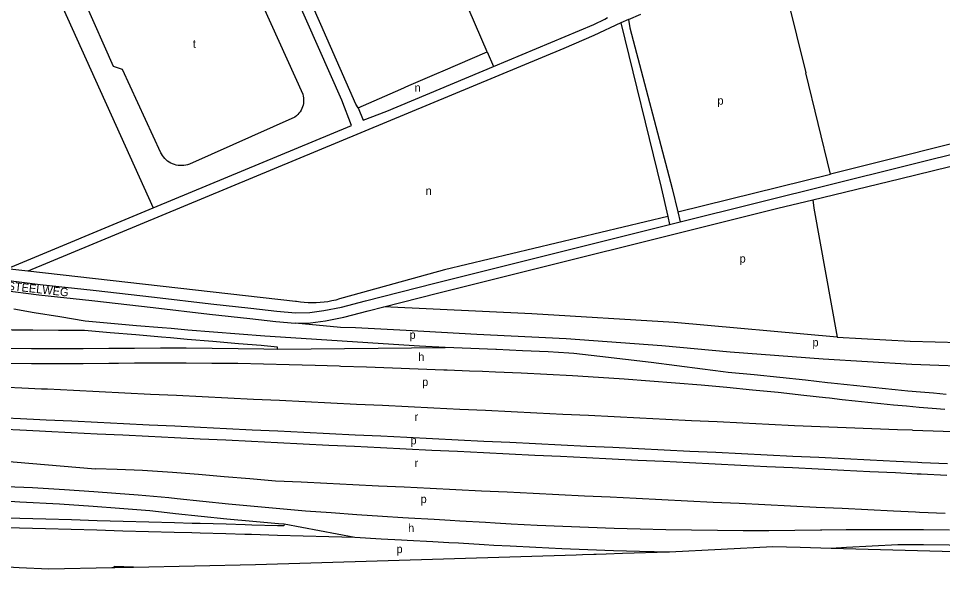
# Model space of a CAD drawing. Extents: x 161093 to 163177, y 379000 to 380904.
# Drawn here: x 161621 to 162069, y 379501.4 to 379771.7 of the extents above; entities that cross this region are included whole.
import ezdxf

# ---------------------------------------------------------------- set-up
doc = ezdxf.new("R2010")
doc.units = 0
for name, color, linetype in [('BLT_Basislijn', 7, 'Continuous'), ('BLT_Centroide', 7, 'Continuous'), ('BLT_Gemeentegrens', 7, 'Continuous'), ('BLT_Hoogspanningsmast_en_leidingen', 7, 'Continuous'), ('BLT_Straatnaam_verkleind', 7, 'Continuous'), ('BLT_Vlakafsluiter', 7, 'Continuous')]:
    doc.layers.add(name, color=color, linetype=linetype)

msp = doc.modelspace()

# ---------------------------------------------------------------- linework, layer by layer
at = {"layer": 'BLT_Basislijn'}
for p, q in [((161631.7, 379800.84), (161686.42, 379679.79)), ((161992.33, 379787.49), (162002.81, 379745.28)), ((161916.83, 379771.19), (161922.76, 379773.7)), ((161916.83, 379771.19), (161912.99, 379769.51)), ((161848.26, 379755.5), (161851.28, 379748.35)), ((162014.73, 379696.21), (162002.81, 379745.28)), ((161755.03, 379723.83), (161703.94, 379701.04)), ((161940.66, 379677.86), (162014.73, 379696.21)), ((161941.83, 379673), (162015.88, 379691.47)), ((161615.34, 379650.24), (161686.42, 379679.79)), ((161935.83, 379675.66), (161827.59, 379649.74)), ((161935.83, 379675.66), (161936.74, 379671.73)), ((161940.66, 379677.86), (161941.83, 379673)), ((161822.91, 379643.33), (161936.74, 379671.73)), ((161936.74, 379671.73), (161941.83, 379673)), ((161625.61, 379649.08), (161615.34, 379650.24)), ((161755.33, 379634.38), (161625.61, 379649.08)), ((161827.59, 379649.74), (161778.52, 379636.18)), ((162054.48, 379571.89), (162115.85, 379569.9)), ((161607.31, 379557.54), (161658.4, 379553.21))]:
    msp.add_line(p, q, dxfattribs=at)
for points in [[(161716.02, 379826.76), (161726.38, 379805.69), (161724.49, 379804.29), (161729.14, 379793.95), (161731.73, 379795.11), (161758.83, 379734.88)], [(161848.26, 379755.5), (161830.87, 379796.01), (161818.6, 379824.68)], [(161686.42, 379679.79), (161782.48, 379719.76), (161777.79, 379732.06), (161743.21, 379810.26)], [(161785.66, 379728.39), (161784.58, 379730.09), (161767.66, 379768.76), (161749.52, 379809.87)], [(161690.13, 379706.56), (161671.49, 379746.97), (161667.17, 379748.31), (161653.31, 379779.49), (161654.88, 379780.21), (161652.16, 379786.35)], [(161912.99, 379769.51), (161900, 379763.42), (161885.43, 379757.17), (161625.61, 379649.08)], [(161851.28, 379748.35), (161900, 379768.76), (161905.26, 379771.38), (161906.6, 379772.15)], [(161912.99, 379769.51), (161932.64, 379689.6), (161935.83, 379675.66)], [(161916.83, 379771.19), (161917.41, 379767.19), (161937.92, 379689.22), (161940.66, 379677.86)], [(161785.66, 379728.39), (161806.4, 379737.35), (161810.28, 379739.08), (161823.92, 379744.93), (161827, 379746.26), (161848.26, 379755.5)], [(161785.66, 379728.39), (161788.11, 379722.31), (161799.58, 379726.7), (161851.28, 379748.35)], [(162185.61, 379741.33), (162185.91, 379739.2), (162185.61, 379738.96), (162014.73, 379696.21)], [(162015.88, 379691.47), (162187.88, 379734.37), (162189.84, 379735.93), (162191.1, 379738.2), (162190.48, 379742.58)], [(161758.83, 379734.88), (161759.06, 379734.02), (161759.2, 379733.15), (161759.27, 379732.26), (161759.26, 379731.37), (161759.17, 379730.49), (161759, 379729.61), (161758.75, 379728.76), (161758.42, 379727.93), (161758.03, 379727.14), (161757.56, 379726.38), (161757.03, 379725.67), (161756.43, 379725.01), (161755.78, 379724.41), (161755.03, 379723.83)], [(162006.2, 379683.74), (162048.1, 379693.81), (162112.09, 379709.59), (162189.91, 379729.16), (162191.71, 379729.23), (162193.12, 379728.84), (162194.49, 379728.03)], [(161703.94, 379701.04), (161703.06, 379700.73), (161702.15, 379700.51), (161701.24, 379700.36), (161700.31, 379700.29), (161699.38, 379700.3), (161698.45, 379700.39), (161697.53, 379700.56), (161696.64, 379700.81), (161695.76, 379701.13), (161694.92, 379701.53), (161694.11, 379702), (161693.35, 379702.53), (161692.64, 379703.13), (161691.98, 379703.79), (161691.38, 379704.5), (161690.84, 379705.26), (161690.37, 379706.07), (161690.13, 379706.56)], [(161824.15, 379638.49), (161989.17, 379679.65), (162006.2, 379683.74)], [(162006.2, 379683.74), (162006.66, 379679.64), (162018.02, 379617.13)], [(161543.41, 379661.1), (161543.58, 379656.98), (161544.04, 379655.38), (161544.67, 379654.3), (161545.55, 379653.27), (161546.57, 379652.45), (161548.53, 379651.99), (161558.56, 379650.79), (161577.45, 379648.89), (161598.58, 379646.57), (161613.83, 379644.81), (161631.56, 379642.59), (161657.22, 379639.82), (161686.97, 379636.4), (161714.22, 379633.26), (161733.73, 379631.1), (161746.36, 379629.63), (161755.31, 379628.82), (161762.24, 379629.08), (161769.08, 379629.98), (161777.69, 379631.61), (161789.34, 379634.73), (161822.91, 379643.33)], [(161540.83, 379645.85), (161541.44, 379646.81), (161542.32, 379647.33), (161543.43, 379647.57), (161558.02, 379645.82), (161576.93, 379643.92), (161598.02, 379641.6), (161613.23, 379639.84), (161630.98, 379637.62), (161656.67, 379634.85), (161686.4, 379631.43), (161713.66, 379628.29), (161733.17, 379626.14), (161745.84, 379624.66), (161755.18, 379623.81)], [(161798.19, 379631.84), (161824.15, 379638.49)], [(161778.52, 379636.18), (161776.69, 379635.6), (161774.84, 379635.08), (161772.97, 379634.65), (161771.08, 379634.29), (161769.18, 379634.01), (161767.27, 379633.81), (161765.36, 379633.69), (161763.44, 379633.66), (161761.52, 379633.7), (161759.6, 379633.82), (161757.69, 379634.02), (161755.8, 379634.3), (161755.33, 379634.38)], [(161827.87, 379612.14), (161815.39, 379612.75), (161802.91, 379613.53), (161790.44, 379614.36), (161777.97, 379615.1), (161765.49, 379615.89), (161753.02, 379616.73), (161740.56, 379617.61), (161728.1, 379618.53), (161715.64, 379619.5), (161703.18, 379620.51), (161695, 379621.2), (161690.73, 379621.57), (161678.27, 379622.63), (161665.82, 379623.7), (161653.36, 379624.76), (161641.03, 379626.86), (161628.66, 379628.95), (161618.77, 379630.63)], [(161755.18, 379623.81), (161762.66, 379624.09), (161769.87, 379625.04), (161778.8, 379626.74), (161790.61, 379629.9), (161798.19, 379631.84)], [(162018.02, 379617.13), (161938.9, 379624.15), (161869.92, 379628.37), (161798.19, 379631.84)], [(161746.67, 379611.27), (161746.7, 379612.27), (161740.2, 379612.82), (161738.77, 379612.95), (161727.74, 379613.89), (161715.29, 379614.95), (161702.83, 379616.02), (161694.81, 379616.7), (161690.38, 379617.08), (161677.92, 379618.15), (161665.47, 379619.21), (161653.01, 379620.28), (161640.48, 379620.36), (161627.94, 379620.45), (161617.91, 379620.52), (161615.42, 379620.73), (161602.96, 379621.8), (161598.16, 379622.21), (161590.51, 379622.86), (161580.54, 379623.71), (161578.05, 379623.93), (161565.6, 379624.99), (161553.14, 379626.06)], [(162154.44, 379587.46), (162154.31, 379590.38), (162153.73, 379592.07), (162152.3, 379593.86), (162150.56, 379595.82), (162148.24, 379598.09), (162146.65, 379599.3), (162145.28, 379599.99), (162141.64, 379600.52), (162121.07, 379601.52), (162089.29, 379602.54), (162054.12, 379603.88), (162011.17, 379606.32), (161966.06, 379609.87), (161932.99, 379612.83), (161886.58, 379616.22), (161843.25, 379618.32), (161808.99, 379620.26), (161784.42, 379621.55), (161777.14, 379621.71)], [(162018.02, 379617.13), (162053.26, 379615.11), (162101.88, 379613.84), (162118.38, 379613.34), (162131.74, 379613.09), (162132.12, 379609.94), (162171.47, 379608.91)], [(161542.18, 379613.94), (161544.61, 379613.83), (161552.7, 379613.46), (161565.15, 379612.97), (161577.6, 379612.55), (161590.06, 379612.21), (161602.52, 379611.94), (161614.67, 379611.74), (161614.98, 379611.74), (161627.44, 379611.61), (161639.9, 379611.55), (161652.36, 379611.57), (161664.82, 379611.66), (161669.47, 379611.71), (161677.33, 379611.79), (161689.86, 379611.87), (161702.4, 379611.86), (161714.94, 379611.79), (161727.48, 379611.64), (161740.02, 379611.42), (161746.67, 379611.27)], [(162070.81, 379589.33), (162064.6, 379589.84), (162058.4, 379590.38), (162052.2, 379590.94), (162052.19, 379590.94), (162046, 379591.52), (162039.81, 379592.13), (162033.62, 379592.76), (162027.42, 379593.41), (162021.24, 379594.08), (162015.05, 379594.78), (162013.19, 379594.99), (162002.6, 379596.19), (161990.14, 379597.53), (161977.66, 379598.8), (161965.18, 379600), (161962.68, 379600.23), (161952.73, 379601.6), (161940.28, 379603.24), (161927.82, 379604.81), (161915.34, 379606.31), (161902.86, 379607.73), (161890.36, 379609.08), (161887.86, 379609.35), (161877.82, 379609.89), (161865.33, 379610.51), (161852.84, 379611.05), (161852.47, 379611.06), (161840.36, 379611.57), (161827.87, 379612.14)], [(161614.85, 379604.49), (161627.35, 379604.36), (161639.85, 379604.3), (161652.36, 379604.32), (161664.86, 379604.41), (161669.53, 379604.46), (161677.36, 379604.55), (161689.85, 379604.62), (161702.35, 379604.62), (161714.85, 379604.54), (161727.34, 379604.4), (161739.84, 379604.18), (161752.33, 379603.88), (161764.83, 379603.52), (161776.48, 379603.11), (161777.32, 379603.08), (161789.81, 379602.61), (161802.3, 379602.15), (161814.79, 379601.68), (161827.28, 379601.21), (161828.86, 379601.15), (161839.77, 379600.74), (161846.02, 379600.51), (161852.26, 379600.26), (161864.75, 379599.72), (161877.23, 379599.11), (161889.71, 379598.42), (161902.18, 379597.66), (161914.65, 379596.83), (161927.12, 379595.93), (161939.58, 379594.95), (161952.03, 379593.9), (161964.48, 379592.78), (161976.92, 379591.59), (161989.35, 379590.32), (162001.77, 379588.99), (162012.33, 379587.79), (162014.19, 379587.58), (162020.41, 379586.88), (162026.62, 379586.2), (162032.84, 379585.55), (162039.06, 379584.91), (162045.28, 379584.31), (162051.5, 379583.72), (162051.5, 379583.72), (162057.73, 379583.16), (162063.96, 379582.62), (162070.19, 379582.1)], [(162054.48, 379571.89), (162047.21, 379572.14), (162034.72, 379572.64), (162022.23, 379573.13), (162009.74, 379573.63), (161997.25, 379574.13), (161984.76, 379574.74), (161972.28, 379575.34), (161959.79, 379575.95), (161947.31, 379576.56), (161934.82, 379577.17), (161922.34, 379577.78), (161909.85, 379578.39), (161897.37, 379579), (161884.88, 379579.6), (161872.4, 379580.21), (161859.91, 379580.82), (161847.43, 379581.43), (161834.94, 379582.04), (161822.46, 379582.65), (161809.97, 379583.26), (161797.49, 379583.86), (161785, 379584.47), (161772.52, 379585.08), (161760.03, 379585.69), (161747.55, 379586.3), (161735.06, 379586.91), (161722.58, 379587.52), (161710.09, 379588.12), (161697.6, 379588.73), (161685.12, 379589.34), (161672.63, 379589.95), (161660.15, 379590.56), (161647.66, 379591.17), (161635.18, 379591.78), (161632.16, 379591.92), (161622.69, 379592.38), (161615.75, 379592.72)], [(161615.03, 379577.99), (161621.98, 379577.65), (161631.44, 379577.19), (161634.46, 379577.04), (161646.95, 379576.43), (161659.43, 379575.83), (161671.92, 379575.22), (161684.4, 379574.61), (161696.89, 379574), (161709.37, 379573.39), (161721.86, 379572.78), (161734.34, 379572.17), (161746.83, 379571.57), (161759.31, 379570.96), (161771.8, 379570.35), (161784.28, 379569.74), (161796.77, 379569.13), (161809.25, 379568.52), (161821.74, 379567.91), (161834.22, 379567.31), (161846.71, 379566.7), (161859.19, 379566.09), (161871.68, 379565.48), (161884.16, 379564.87), (161896.65, 379564.26), (161909.13, 379563.65), (161921.62, 379563.05), (161934.11, 379562.44), (161946.59, 379561.83), (161959.08, 379561.22), (161971.56, 379560.61), (161984.05, 379560), (161996.53, 379559.39), (162009.02, 379558.79), (162021.5, 379558.18), (162033.99, 379557.57), (162046.47, 379556.96), (162057.03, 379556.45), (162058.96, 379556.35), (162071.44, 379555.75)], [(161614.76, 379572.4), (161621.7, 379572.06), (161631.17, 379571.6), (161634.19, 379571.45), (161646.67, 379570.84), (161659.16, 379570.23), (161671.64, 379569.62), (161684.13, 379569.02), (161696.61, 379568.41), (161709.1, 379567.8), (161721.58, 379567.19), (161734.07, 379566.58), (161746.55, 379565.97), (161759.04, 379565.36), (161771.53, 379564.76), (161784.01, 379564.15), (161796.5, 379563.54), (161808.98, 379562.93), (161821.47, 379562.32), (161833.95, 379561.71), (161846.44, 379561.1), (161858.92, 379560.5), (161871.41, 379559.89), (161883.89, 379559.28), (161896.38, 379558.67), (161908.86, 379558.06), (161921.35, 379557.45), (161933.83, 379556.84), (161946.32, 379556.24), (161958.8, 379555.63), (161971.29, 379555.02), (161983.77, 379554.41), (161996.26, 379553.8), (162008.74, 379553.19), (162021.23, 379552.58), (162033.71, 379551.98), (162046.2, 379551.37), (162056.76, 379550.85), (162058.68, 379550.76), (162071.17, 379550.16)], [(161695.79, 379551.48), (161681.14, 379552.37), (161668.91, 379552.86), (161658.4, 379553.21)], [(162070.29, 379531.48), (162057.78, 379532.08), (162055.85, 379532.17), (162045.29, 379532.69), (162032.8, 379533.3), (162020.32, 379533.91), (162007.83, 379534.51), (161995.35, 379535.12), (161982.86, 379535.73), (161970.38, 379536.34), (161957.89, 379536.95), (161945.41, 379537.56), (161932.92, 379538.17), (161920.44, 379538.77), (161907.95, 379539.38), (161895.47, 379539.99), (161882.98, 379540.6), (161870.5, 379541.21), (161858.01, 379541.82), (161845.53, 379542.43), (161833.04, 379543.03), (161820.56, 379543.64), (161808.07, 379544.25), (161795.59, 379544.86), (161783.1, 379545.47), (161770.61, 379546.08), (161758.13, 379546.69), (161745.64, 379547.29), (161733.18, 379548.34), (161720.72, 379549.39), (161708.25, 379550.43), (161695.79, 379551.48)], [(161615.1, 379544.66), (161627.84, 379544.08), (161643.38, 379543.21), (161657.63, 379542.23), (161668.24, 379541.42), (161679.07, 379540.56), (161693.92, 379539.23), (161697.97, 379538.79), (161710.39, 379537.47), (161722.83, 379536.22), (161735.27, 379535.04), (161747.72, 379533.94), (161760.17, 379532.9), (161772.63, 379531.94), (161785.1, 379531.05), (161797.57, 379530.23), (161807.41, 379529.63), (161810.05, 379529.47), (161822.52, 379528.74), (161830.38, 379528.28), (161835, 379528.01), (161847.48, 379527.28), (161852.12, 379527.01), (161859.96, 379526.56), (161872.44, 379525.91), (161884.92, 379525.34), (161897.41, 379524.83), (161909.9, 379524.4), (161922.39, 379524.04), (161934.89, 379523.76), (161947.38, 379523.54), (161959.88, 379523.4), (161972.38, 379523.33), (161984.87, 379523.34), (161997.37, 379523.42), (162009.87, 379523.57), (162010.56, 379523.58), (162022.37, 379523.72), (162034.87, 379523.81), (162047.37, 379523.82), (162059.88, 379523.76), (162072.38, 379523.63)], [(161530.82, 379543.1), (161533.84, 379542.95), (161544.77, 379542.28), (161555.76, 379541.42), (161580.23, 379539.92), (161604.27, 379538.4), (161621.66, 379537.24), (161640.93, 379536.15), (161657.33, 379535.14), (161669.99, 379534.16), (161684.77, 379532.93), (161693.12, 379532.02), (161697.18, 379531.58), (161709.65, 379530.26), (161722.13, 379529), (161734.61, 379527.82), (161747.1, 379526.72), (161749.8, 379526.49)], [(161749.8, 379526.49), (161749.71, 379525.5), (161746.69, 379525.58), (161734.2, 379525.93), (161730.94, 379526.02), (161721.7, 379526.28), (161709.21, 379526.63), (161705.26, 379526.74), (161696.71, 379526.98), (161684.22, 379527.34), (161671.72, 379527.69), (161659.23, 379528.04), (161646.73, 379528.39), (161634.24, 379528.74), (161621.74, 379529.09), (161609.25, 379529.44)], [(161609.12, 379524.94), (161621.62, 379524.59), (161634.11, 379524.24), (161646.61, 379523.89), (161659.1, 379523.54), (161671.6, 379523.19), (161684.09, 379522.84), (161696.59, 379522.49), (161705.13, 379522.25), (161709.08, 379522.14), (161721.58, 379521.78), (161730.82, 379521.52), (161734.07, 379521.43), (161746.57, 379521.08), (161759.06, 379520.73), (161771.56, 379520.38), (161784.05, 379520.03)], [(161784.05, 379520.03), (161796.87, 379519.2), (161806.77, 379518.69), (161809.41, 379518.57), (161821.89, 379517.96), (161829.75, 379517.5), (161834.37, 379517.23), (161846.85, 379516.5), (161851.49, 379516.23), (161859.37, 379515.78), (161871.91, 379515.13), (161884.46, 379514.55), (161897.01, 379514.04), (161909.56, 379513.61), (161922.11, 379513.25), (161936.33, 379512.92)], [(162015.03, 379514.73), (162022.45, 379515.17), (162034.9, 379515.85), (162047.36, 379516.45), (162049.85, 379516.57), (162059.82, 379516.51), (162072.28, 379516.38), (162084.74, 379516.18), (162086.23, 379516.15), (162097.2, 379515.9), (162109.65, 379515.55), (162111.99, 379515.47)]]:
    msp.add_lwpolyline(points, dxfattribs=at)
at = {"layer": 'BLT_Gemeentegrens'}
for points in [[(161535.22, 379503.34), (161535.68, 379503.96), (161585.89, 379507.02), (161615.55, 379505.69), (161618.63, 379505.53), (161621.36, 379505.38), (161635.7, 379504.63), (161666.33, 379505.31), (161667.77, 379505.34), (161676.74, 379505.54), (161735.99, 379506.87), (161891.41, 379511.56), (161894.5, 379511.66), (161900, 379511.82), (161900.14, 379511.83), (161901.03, 379511.85), (161905.93, 379512), (161913.88, 379512.24), (161936.33, 379512.92)], [(161936.33, 379512.92), (161936.59, 379512.93), (161986.73, 379515.5), (162000, 379515.14), (162015.03, 379514.73)], [(162015.03, 379514.73), (162086.74, 379512.78), (162110.7, 379501.44)]]:
    msp.add_lwpolyline(points, dxfattribs=at)
at = {"layer": 'BLT_Hoogspanningsmast_en_leidingen'}
msp.add_line((161667.36, 379505.77), (161667.77, 379505.34), dxfattribs=at)
msp.add_lwpolyline([(161676.74, 379505.54), (161667.36, 379505.77), (161667.35, 379505.33)], dxfattribs=at)
at = {"layer": 'BLT_Vlakafsluiter'}
for p, q in [((161777.14, 379621.71), (161755.18, 379623.81)), ((161746.67, 379611.27), (161827.87, 379612.14)), ((161749.8, 379526.49), (161784.05, 379520.03))]:
    msp.add_line(p, q, dxfattribs=at)

# ---------------------------------------------------------------- texts
at = {"layer": 'BLT_Centroide'}
for s, p in [('t', (161705.55, 379757.42)), ('n', (161813.03, 379736.15)), ('p', (161959.89, 379729.87)), ('n', (161818.43, 379686.1)), ('p', (161970.63, 379653.22)), ('p', (161810.62, 379616.28)), ('p', (162005.96, 379612.55)), ('h', (161814.84, 379605.56)), ('p', (161816.74, 379593.41)), ('r', (161813.03, 379576.48)), ('p', (161811.09, 379565.07)), ('r', (161813.03, 379554.04)), ('p', (161815.98, 379536.58)), ('h', (161809.93, 379522.53)), ('p', (161804.31, 379512.32))]:
    msp.add_text(s, height=4, dxfattribs=at).set_placement(p)
at = {"layer": 'BLT_Straatnaam_verkleind'}
msp.add_text('VAN DER BEKEN PASTEELWEG', height=3.9999, rotation=353.5595, dxfattribs=at).set_placement((161563.88, 379645.93))

doc.saveas('drawing.dxf')
